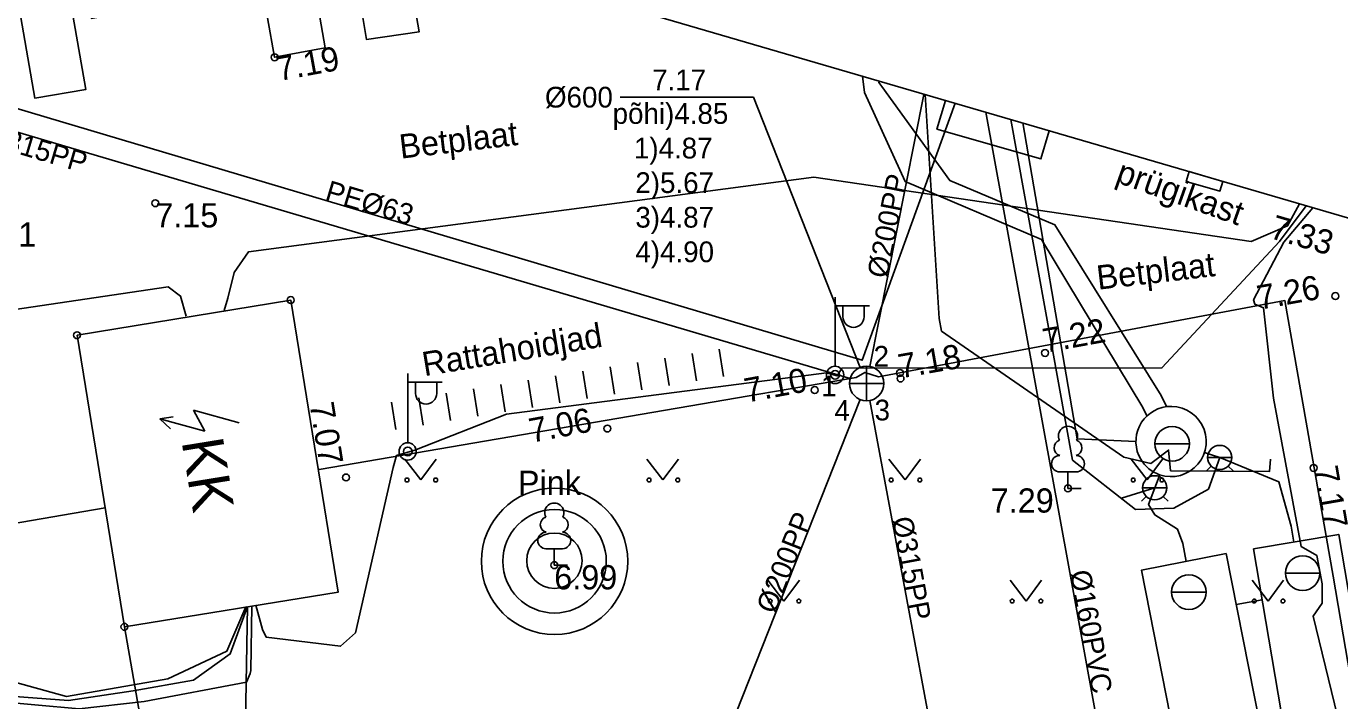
# Model space of a CAD drawing. Extents: x 473307 to 473719, y 6532843 to 6533381.
# Drawn here: x 473546.03 to 473584.01, y 6532963.02 to 6532982.52 of the extents above; entities that cross this region are included whole.
import ezdxf

# ---------------------------------------------------------------- set-up
doc = ezdxf.new("R2010")
doc.units = 0
for name, color, linetype in [('Default', 7, 'Continuous'), ('HALJASTUS', 7, 'Continuous'), ('HOONE', 7, 'Continuous'), ('KORGUS', 7, 'Continuous'), ('KPKAABEL', 7, 'Continuous'), ('KTRASS', 7, 'Continuous'), ('KTRASS_TEKST', 7, 'Continuous'), ('MPKAABEL', 7, 'Continuous'), ('POST', 7, 'Continuous'), ('PUU', 7, 'Continuous'), ('RAJATIS', 7, 'Continuous'), ('SKKAEV', 7, 'Continuous'), ('SKKAEV_NR', 7, 'Continuous'), ('SKTRASS', 7, 'Continuous'), ('SKTRASS_TEKST', 7, 'Continuous'), ('TEE', 7, 'Continuous'), ('VKAEV', 7, 'Continuous'), ('VTRASS', 7, 'Continuous'), ('VTRASS_TEKST', 7, 'Continuous')]:
    doc.layers.add(name, color=color, linetype=linetype)

# ---------------------------------------------------------------- blocks, each defined once
blk = doc.blocks.new('AJ')
at = {"layer": 'Default'}
for p, q in [((0.952, 4.493), (-0.185, 2.009)), ((-0.185, 2.009), (1.111, 2.458)), ((1.111, 2.458), (0, 0)), ((0, 0.793), (0, 0)), ((0, 0), (0.661, 0.529))]:
    blk.add_line(p, q, dxfattribs=at)
blk = doc.blocks.new('MEPOST')
at = {"layer": 'Default'}
blk.add_circle((0, 0), 0.5, dxfattribs=at)
for start, end in [(0, 180), (180, 0)]:
    blk.add_arc((0, 0), 0.25, start, end, dxfattribs=at)
blk = doc.blocks.new('VAPOST')
at = {"layer": 'Default'}
for p, q in [((0, 0.5), (0, 4.5)), ((0, 4), (2, 4)), ((0.453, 3.358), (0.453, 4)), ((1.679, 3.358), (1.679, 4))]:
    blk.add_line(p, q, dxfattribs=at)
blk.add_arc((1.066, 3.358), 0.613, 180, 0, dxfattribs=at)
blk = doc.blocks.new('KAKAEV')
at = {"layer": 'Default'}
for p, q in [((0, -1), (0, 1)), ((-1, 0), (1, 0))]:
    blk.add_line(p, q, dxfattribs=at)
blk.add_circle((0, 0), 1, dxfattribs=at)
blk = doc.blocks.new('VESIIB')
at = {"layer": 'Default'}
for p, q in [((-0.7, 0), (0.7, 0)), ((-0.495, -0.495), (-0.774, -0.774)), ((0.495, -0.495), (0.774, -0.774))]:
    blk.add_line(p, q, dxfattribs=at)
blk.add_circle((0, 0), 0.7, dxfattribs=at)
blk = doc.blocks.new('VEKAEV')
at = {"layer": 'Default'}
blk.add_line((-1, 0), (1, 0), dxfattribs=at)
blk.add_circle((0, 0), 1, dxfattribs=at)
blk = doc.blocks.new('MURU')
at = {"layer": 'Default'}
for p, q in [((-0.927, 1.213), (0, 0)), ((0, 0), (0.891, 1.213))]:
    blk.add_line(p, q, dxfattribs=at)
for centre in [(-0.802, 0), (0.856, 0)]:
    blk.add_circle(centre, 0.11, dxfattribs=at)
blk = doc.blocks.new('LEHTP1')
at = {"layer": 'Default'}
for p, q in [((0.48, 0.95), (-0.48, 0.95)), ((0, 0), (0, 0.95)), ((0.76, 0), (0, 0))]:
    blk.add_line(p, q, dxfattribs=at)
for centre, radius, start, end in [((0, 3.04), 0.554, 332.5799, 207.4201), ((-0.34, 2.345), 0.465, 109.02174, 253.14154), ((0.34, 2.345), 0.465, 286.85082, 70.98591), ((-0.475, 1.425), 0.475, 90.0016, 269.3953), ((0.475, 1.425), 0.475, 270.6047, 89.9984)]:
    blk.add_arc(centre, radius, start, end, dxfattribs=at)

msp = doc.modelspace()

# ---------------------------------------------------------------- linework, layer by layer
at = {"layer": 'HOONE'}
for points in [[(473585.831, 6533013.369), (473574.881, 6533011.486), (473566.132, 6533009.962), (473540.511, 6533005.576), (473543.395, 6532988.91), (473585.455, 6532976.623), (473588.828, 6532956.753), (473587.886, 6532956.595), (473589.164, 6532949.286), (473629.221, 6532956.166), (473626.335, 6532972.834), (473619.836, 6532974.765), (473602.305, 6532979.874), (473597.625, 6532979.18), (473590.334, 6532981.418), (473586.157, 6533005.917), (473587.084, 6533006.076)], [(473547.497, 6532973.586), (473553.675, 6532974.602), (473555.047, 6532966.156), (473548.867, 6532965.152)]]:
    msp.add_lwpolyline(points, close=True, dxfattribs=at)
at = {"layer": 'KORGUS'}
for centre in [(473553.208, 6532981.623), (473549.759, 6532977.404), (473553.675, 6532974.602), (473583.883, 6532974.717), (473547.497, 6532973.586), (473575.488, 6532973.072), (473571.292, 6532972.496), (473571.308, 6532972.334), (473568.827, 6532972), (473562.832, 6532970.887), (473555.274, 6532969.472), (473583.251, 6532969.749), (473576.15, 6532969.156), (473561.295, 6532966.936), (473548.867, 6532965.152)]:
    msp.add_circle(centre, 0.1, dxfattribs=at)
at = {"layer": 'KPKAABEL'}
for points in [[(473552.428, 6532965.743), (473551.926, 6532964.369), (473550.859, 6532963.61), (473549.116, 6532963.304), (473547.25, 6532963.025), (473541.17, 6532963.479), (473534.383, 6532967.06), (473529.823, 6532970.204), (473517.524, 6532979.079), (473506.639, 6532987.521), (473501.292, 6532992.893), (473495.73, 6532998.121), (473498.407, 6533003.379)], [(473552.428, 6532965.743), (473552.248, 6532955.743), (473551.396, 6532952.25), (473548.538, 6532944.595), (473546.922, 6532939.52), (473555.37, 6532934.798), (473562.977, 6532930.797), (473573.936, 6532926.157), (473585.002, 6532921.176), (473597.713, 6532916.33), (473608.101, 6532913.364), (473620.133, 6532910.115), (473635.44, 6532908.143), (473647.319, 6532907.126), (473658.175, 6532907.682), (473669.898, 6532907.954), (473678.245, 6532908.166), (473679.837, 6532908.723), (473681.3, 6532908.756), (473682.619, 6532907.437), (473683.14, 6532903.797)]]:
    msp.add_lwpolyline(points, dxfattribs=at)
at = {"layer": 'KTRASS'}
msp.add_lwpolyline([(473573.778, 6532980.035), (473580.221, 6532944.7)], dxfattribs=at)
at = {"layer": 'MPKAABEL'}
for points in [[(473550.647, 6532974.134), (473550.491, 6532974.716), (473550.13, 6532974.982), (473530.273, 6532972.046), (473510.168, 6532985.169), (473499.773, 6532994.387), (473488.127, 6533008.236)], [(473488.425, 6533006.486), (473501.71, 6533000.864), (473517.757, 6532996.211), (473517.757, 6532996.211), (473517.757, 6532996.211), (473533.632, 6532991.468), (473540.569, 6532989.326), (473541.046, 6532988.945), (473541.043, 6532988.058), (473544.258, 6532969.621), (473543.338, 6532964.734), (473543.314, 6532964.208), (473547.196, 6532963.14), (473550.121, 6532963.651), (473551.828, 6532964.446), (473552.375, 6532965.735)], [(473493.252, 6532975.715), (473497.24, 6532978.112), (473498.183, 6532979.06), (473499.269, 6532980.163), (473501.448, 6532982.423), (473503.504, 6532984.545), (473505.843, 6532986.884), (473507.45, 6532987.966), (473517.665, 6532979.32), (473529.752, 6532970.098), (473534.316, 6532966.914), (473541.139, 6532963.364), (473547.56, 6532962.777), (473549.436, 6532962.995), (473552.396, 6532963.548), (473552.501, 6532963.798), (473552.517, 6532963.893), (473552.555, 6532965.764)], [(473572.022, 6532980.547), (473572.429, 6532974.068), (473572.493, 6532973.705), (473577.762, 6532970.055), (473578.545, 6532969.876), (473579.061, 6532970.263), (473579.117, 6532969.664), (473581.974, 6532969.641), (473582.009, 6532970.001)], [(473574.494, 6532979.825), (473576.278, 6532969.976), (473578.105, 6532968.548), (473579.207, 6532968.581), (473580.216, 6532969.134), (473580.539, 6532970.05)], [(473578.114, 6532970.513), (473576.42, 6532970.588), (473574.841, 6532979.724)], [(473551.753, 6532974.305), (473551.855, 6532974.661), (473552.035, 6532975.395), (473552.453, 6532975.994), (473568.802, 6532978.161), (473581.445, 6532976.295), (473582.499, 6532976.75), (473582.848, 6532977.385)], [(473583.036, 6532977.33), (473582.263, 6532976.301), (473578.865, 6532972.641), (473569.606, 6532972.63), (473569.476, 6532972.41), (473569.476, 6532972.41), (473569.168, 6532972.502), (473559.918, 6532971.304), (473557.263, 6532970.26), (473556.731, 6532970.106), (473556.638, 6532969.756), (473555.549, 6532964.979), (473555.115, 6532964.593), (473555.115, 6532964.593), (473555.115, 6532964.593), (473552.963, 6532964.857), (473552.86, 6532965.071), (473552.665, 6532965.781)], [(473583.229, 6532977.274), (473582.388, 6532976.276), (473581.518, 6532974.611), (473581.518, 6532974.611), (473581.55, 6532974.485), (473581.806, 6532974.382), (473582.092, 6532971.765), (473582.897, 6532967.472), (473583.344, 6532967.218), (473583.499, 6532966.399), (473583.498, 6532965.835), (473583.235, 6532965.46), (473587.471, 6532948.068)], [(473578.659, 6532969.173), (473577.694, 6532968.869)]]:
    msp.add_lwpolyline(points, dxfattribs=at)
at = {"layer": 'RAJATIS'}
for points in [[(473579.658, 6532978.319), (473579.57, 6532978.029), (473580.542, 6532977.756), (473580.63, 6532978.031), (473579.658, 6532978.319)], [(473565.407, 6532972.264), (473565.279, 6532973.054)], [(473566.188, 6532972.39), (473566.061, 6532973.18)], [(473563.037, 6532971.881), (473562.91, 6532972.671)], [(473563.827, 6532972.009), (473563.7, 6532972.798)], [(473564.617, 6532972.136), (473564.489, 6532972.926)], [(473560.668, 6532971.498), (473560.541, 6532972.288)], [(473561.458, 6532971.626), (473561.33, 6532972.416)], [(473562.248, 6532971.754), (473562.12, 6532972.543)], [(473558.299, 6532971.116), (473558.171, 6532971.906)], [(473559.089, 6532971.243), (473558.961, 6532972.033)], [(473559.878, 6532971.371), (473559.751, 6532972.161)], [(473556.719, 6532970.861), (473556.592, 6532971.65)], [(473557.509, 6532970.988), (473557.381, 6532971.778)]]:
    msp.add_lwpolyline(points, dxfattribs=at)
for centre, radius in [((473561.304, 6532967.048), 2.117), ((473561.304, 6532967.048), 1.496), ((473561.299, 6532967.065), 0.801)]:
    msp.add_circle(centre, radius, dxfattribs=at)
at = {"layer": 'SKKAEV_NR'}
msp.add_lwpolyline([(473570.144, 6532972.657), (473567.054, 6532980.47), (473563.199, 6532980.47)], dxfattribs=at)
at = {"layer": 'SKTRASS'}
for points in [[(473512.927, 6532989.185), (473569.849, 6532972.334)], [(473570.425, 6532972.682), (473571.983, 6532980.546)], [(473565.412, 6532959.776), (473570.144, 6532971.727)], [(473570.419, 6532971.7), (473573.302, 6532956.194)]]:
    msp.add_lwpolyline(points, dxfattribs=at)
at = {"layer": 'TEE'}
for points in [[(473556.963, 6532984.802), (473556.963, 6532984.802), (473556.963, 6532984.802), (473556.963, 6532984.802), (473557.385, 6532982.357), (473555.863, 6532982.14), (473555.342, 6532985.275), (473554.052, 6532985.454), (473554.673, 6532981.893), (473553.208, 6532981.623), (473552.392, 6532986.183), (473551.893, 6532986.227), (473552.341, 6532983.523), (473550.847, 6532983.274), (473550.268, 6532986.692), (473548.72, 6532987.053), (473549.36, 6532983.022), (473547.91, 6532982.748), (473547.02, 6532987.68), (473546.53, 6532987.705), (473547.752, 6532980.694), (473546.271, 6532980.446), (473544.878, 6532988.45), (473543.56, 6532988.745)], [(473572.604, 6532980.377), (473572.362, 6532979.548), (473575.368, 6532978.684), (473575.606, 6532979.5)], [(473554.501, 6532969.707), (473570.029, 6532972.36), (473570.276, 6532972.512), (473570.673, 6532972.387), (473582.421, 6532974.587), (473583.816, 6532966.613), (473585.244, 6532958.249), (473587.257, 6532946.609), (473594.954, 6532947.911), (473595.461, 6532945.145)], [(473538.549, 6532966.914), (473548.313, 6532968.59)], [(473549.913, 6532959.174), (473548.867, 6532965.152)]]:
    msp.add_lwpolyline(points, dxfattribs=at)
at = {"layer": 'VTRASS'}
for points in [[(473503.152, 6532977.438), (473511.34, 6532985.817), (473514.381, 6532989.489), (473570.194, 6532972.861), (473572.889, 6532980.294)], [(473578.432, 6532971.251), (473578.31, 6532971.497), (473575.389, 6532976.353), (473571.445, 6532978.029), (473571.445, 6532978.029), (473570.267, 6532980.602), (473570.212, 6532981.076)], [(473570.708, 6532980.931), (473570.68, 6532980.893), (473570.769, 6532980.781), (473572.732, 6532978.064), (473575.774, 6532976.778), (473578.842, 6532971.847), (473578.994, 6532971.52)], [(473580.096, 6532970.196), (473580.332, 6532970.118), (473580.539, 6532970.05), (473582.245, 6532969.35), (473582.602, 6532968.059), (473582.679, 6532967.605)], [(473578.799, 6532969.552), (473578.782, 6532969.502)], [(473579.568, 6532967.046), (473579.467, 6532967.558), (473579.32, 6532967.978), (473578.664, 6532968.388), (473578.481, 6532968.693), (473578.782, 6532969.502)], [(473581.017, 6532965.803), (473581.766, 6532965.93)]]:
    msp.add_lwpolyline(points, dxfattribs=at)
for points in [[(473585.934, 6532956.295), (473583.47, 6532955.877), (473581.516, 6532967.408), (473583.98, 6532967.826)], [(473580.727, 6532967.275), (473582.995, 6532955.767), (473580.543, 6532955.283), (473578.275, 6532966.791)]]:
    msp.add_lwpolyline(points, close=True, dxfattribs=at)
for start, end in [(97.6804, 210.542), (251.0038, 97.6804), (210.542, 251.0038)]:
    msp.add_arc((473579.13, 6532970.513), 1.016, start, end, dxfattribs=at)

# ---------------------------------------------------------------- block references
at = {"layer": 'HALJASTUS', "xscale": 0.5, "yscale": 0.5}
for p in [(473557.438, 6532969.399), (473564.438, 6532969.399), (473571.438, 6532969.399), (473578.438, 6532969.399), (473567.938, 6532965.899), (473574.938, 6532965.899), (473581.938, 6532965.899)]:
    msp.add_blockref('MURU', p, dxfattribs=at)
at = {"layer": 'HOONE', "xscale": 0.5, "yscale": 0.5, "rotation": -80.77358858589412}
msp.add_blockref('AJ', (473549.888, 6532971.164), dxfattribs=at)
at = {"layer": 'POST', "xscale": 0.5, "yscale": 0.5}
for name, p in [('VAPOST', (473569.415, 6532972.438)), ('MEPOST', (473569.415, 6532972.438)), ('VAPOST', (473557.057, 6532970.224)), ('MEPOST', (473557.057, 6532970.224))]:
    msp.add_blockref(name, p, dxfattribs=at)
at = {"layer": 'PUU', "xscale": 0.5, "yscale": 0.5}
for p in [(473576.15, 6532969.156), (473561.295, 6532966.936)]:
    msp.add_blockref('LEHTP1', p, dxfattribs=at)
at = {"layer": 'SKKAEV', "xscale": 0.5, "yscale": 0.5}
msp.add_blockref('KAKAEV', (473570.328, 6532972.192), dxfattribs=at)
at = {"layer": 'VKAEV', "xscale": 0.5, "yscale": 0.5}
for name, p in [('VEKAEV', (473579.16, 6532970.447)), ('VESIIB', (473580.539, 6532970.05)), ('VESIIB', (473578.659, 6532969.173)), ('VEKAEV', (473582.935, 6532966.706)), ('VEKAEV', (473579.647, 6532966.157))]:
    msp.add_blockref(name, p, dxfattribs=at)

# ---------------------------------------------------------------- texts
at = {"layer": 'HOONE'}
msp.add_text('KK', height=1.2, rotation=279.2264, dxfattribs=at).set_placement((473550.516, 6532970.521))
at = {"layer": 'KORGUS'}
for s, rotation, p in [('7.19', 10.4317, (473553.335, 6532980.935)), ('7.33', 343.7155, (473581.95, 6532976.404)), ('7.26', 10.2677, (473581.685, 6532974.319)), ('7.22', 10.2677, (473575.488, 6532973.072)), ('7.18', 10.0127, (473571.308, 6532972.334)), ('7.10', 10.5175, (473566.861, 6532971.635)), ('7.07', 279.2704, (473554.218, 6532971.596)), ('7.06', 10.6041, (473560.637, 6532970.476)), ('7.17', 279.8658, (473583.251, 6532969.749))]:
    msp.add_text(s, height=0.7, rotation=rotation, dxfattribs=at).set_placement(p)
for s, p in [('7.15', (473549.759, 6532976.704)), ('7.11', (473544.495, 6532976.15)), ('7.29', (473573.917, 6532968.456)), ('6.99', (473561.295, 6532966.236))]:
    msp.add_text(s, height=0.7, dxfattribs=at).set_placement(p)
at = {"layer": 'KTRASS_TEKST'}
msp.add_text('%%C160PVC', height=0.6, rotation=280.3346, dxfattribs=at).set_placement((473576.202, 6532966.74))
at = {"layer": 'RAJATIS'}
for s, rotation, p in [('prügikast', 340.4421, (473577.496, 6532978.024)), ('Rattahoidjad', 9.418, (473557.539, 6532972.398))]:
    msp.add_text(s, height=0.7, rotation=rotation, dxfattribs=at).set_placement(p)
msp.add_text('Pink', height=0.7, dxfattribs=at).set_placement((473560.244, 6532968.967))
at = {"layer": 'SKKAEV_NR'}
for s, p in [('7.17', (473564.126, 6532980.67)), ('%%C600', (473561.027, 6532980.17)), ('põhi)4.85', (473562.983, 6532979.698)), ('1)4.87', (473563.598, 6532978.698)), ('2)5.67', (473563.64, 6532977.698)), ('3)4.87', (473563.64, 6532976.698)), ('4)4.90', (473563.64, 6532975.698)), ('2', (473570.528, 6532972.676)), ('1', (473569.013, 6532971.816)), ('4', (473569.399, 6532971.112)), ('3', (473570.558, 6532971.121))]:
    msp.add_text(s, height=0.6, dxfattribs=at).set_placement(p)
at = {"layer": 'SKTRASS_TEKST'}
for s, rotation, p in [('%%C315PP', 343.509, (473544.774, 6532979.131)), ('%%C200PP', 78.7956, (473570.925, 6532975.205)), ('%%C200PP', 68.3998, (473567.676, 6532965.495)), ('%%C315PP', 280.5294, (473571.055, 6532968.281))]:
    msp.add_text(s, height=0.6, rotation=rotation, dxfattribs=at).set_placement(p)
at = {"layer": 'TEE'}
for p in [(473556.856, 6532978.69), (473577.019, 6532974.9)]:
    msp.add_text('Betplaat', height=0.7, rotation=6.6667, dxfattribs=at).set_placement(p)
at = {"layer": 'VTRASS_TEKST'}
msp.add_text('PE%%C63', height=0.6, rotation=343.4097, dxfattribs=at).set_placement((473554.634, 6532977.497))

doc.saveas('drawing.dxf')
